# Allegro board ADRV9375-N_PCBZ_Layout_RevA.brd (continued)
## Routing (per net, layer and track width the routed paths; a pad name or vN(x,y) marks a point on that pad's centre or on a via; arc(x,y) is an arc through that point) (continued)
VDD_IF: length 250.6
  TOP w0.203: U403.8 117.21,60.84 v1(117.49,60.57)
  TOP w0.254: U101.M12 v2(38.04,50.78)
  TOP w0.305: U702.1 51.41,16.64 51.01,17.05 ; v1(56.78,24.56) 55.25,26.09 R606.1 ; R739.2 50.3,16.65 ; R808.1 R809.1 137.92,53.04 v2(137.83,52.96) ; R510.1 93.34,49.45 98.32,49.45 100.09,51.22 v1(100.09,52.12) 100.09,52.69 R512.1 ; U702.2 51.35,15.99 51.03,16.31 ; v1(123.51,32.78) 122.53,33.76 U404.1 120.98,33.76 120.51,34.24 120.51,34.57 120.01,35.06 U404.4 ; U405.8 v1(122.74,66.3) ; v1(97.05,57.64) 97.56,57.13 R513.1 ; v1(117.49,60.57) 118.64,60.57 118.84,60.76 U405.1 ; R511.1 v1(94.81,57.64)
  TOP w0.394: v2(132.75,25.02) 132.75,25.02 R503.1 ; P504.1 v1(43.47,72.38)
  TOP w0.508: 47,14.21 P707.1 ; P707.1 45.92,15.29 ; P707.1 48.08,15.29 ; P707.1 47,16.37
  TOP w0.762: v1(131.48,22.48) 131.45,22.45 R738.2
  L3_PWR w0.508: v1(100.09,52.12) 100.09,54.61 v1(97.05,57.64) 97.05,57.93 96.52,58.46 95.64,58.46 v1(94.81,57.64)
  L3_PWR w0.635: 123.51,29.8 v1(123.51,32.78) ; 123.51,29.8 122.21,28.49 119.45,28.49 118.91,27.96 95.23,27.96 93.51,29.67 85.83,29.67 85.37,30.12 80.03,30.12 v1(78.75,31.41) 77.87,31.41 v1(77.86,31.42) v1(77.1,31.42) ; 123.51,29.8 127.04,26.27 131.5,26.27 v2(132.75,25.02) 132.75,23.75 v1(131.48,22.48)
  L12_PWR w0.203: 56.78,22.65 v1(56.78,24.56)
  L12_PWR w0.508: 115.2,53.13 115.2,59.48 116.28,60.57 v1(117.49,60.57) ; 45.92,15.29 P707.1 ; P707.1 48.08,15.29 ; P707.1 47,14.21 ; P707.1 47,16.37 ; v1(122.74,66.3) 122.74,62.49 125.36,59.86 125.36,52.88
  L12_PWR w0.762: 76.08,55.67 48.27,55.67 45.53,52.94 43.63,52.94 41.47,50.78 v2(38.04,50.78) ; v1(43.47,72.38) 45.56,74.47 68.34,74.47 69.99,72.82 69.99,68.5 71.38,67.1 71.38,61.39 72.65,60.12 76.97,60.12 78.5,58.59 78.5,57.7
  BOTTOM w0.305: C642.1 R502.1 ; C642.1 38.05,50.79 v2(38.04,50.78) ; C642.1 38.05,52.33 C643.1
  BOTTOM w0.394: v1(125.61,36.88) 125.61,36.24 123.51,34.14 v1(123.51,32.78) 123.26,32.78 122.7,33.33 C415.2 ; P801.K40 v1(131.48,22.48) ; P801.J39 v2(132.75,25.02) ; v1(122.74,66.3) 122.81,66.23 C417.2
  BOTTOM w0.508: C734.2 49.64,16.06 C735.2
  BOTTOM w0.762: C734.2 48.87,15.29 P707.1
VDD_IF_LDO: length 2.9
  TOP w0.254: U702.5 57.63,14.69 58.1,15.16 58.1,16.32
  TOP w0.305: U702.7 56.66,16.06
  vias: v1(57.41,17.5) v1(58.47,18.72) v1(58.43,17.45) v1(58.94,18.08) v1(59.45,18.72) v1(59.45,17.51)
VDDA_1P8_1: length 8.1
  TOP w0.127: L306.1 36.39,34.2
  TOP w0.394: 36.78,34.2 35.77,34.2 T306.2 T310.2
  TOP w0.508: 36.78,34.2 37.21,34.2 C327.1 37.6,34.21 37.79,34.02 v1(38.57,34.02) v1(38.57,34.73) v1(38.57,35.44)
  BOTTOM w0.508: v1(38.57,34.02) v1(38.57,34.73) v1(38.57,35.44) 38.57,36.81 L341.2
VDDA_1P8_2: length 6.6
  TOP w0.127: L305.1 33.28,59.35
  TOP w0.394: T309.2 T305.2 33.91,59.35 32.9,59.35
  TOP w0.508: 32.9,59.35 32.47,59.35 C322.1 32.05,59.34 31.93,59.22 v1(31.45,59.22) v1(31.45,59.93) v1(31.45,60.64)
  BOTTOM w0.508: v1(31.45,59.22) v1(31.45,59.93) v1(31.45,60.64) 31.46,60.64 L340.2
VDDA_CALPLL: length 17.7
  TOP w0.254: v2(33.24,43.58) U101.G4
  L7_SIG w0.203: v2(33.24,43.58) 33.5,43.58 33.88,43.19 34.16,43.19 34.43,42.93 34.43,41.58
  L7_SIG w0.394: 34.43,41.58 34.43,36.88 33.03,35.48 32.49,35.48 31.89,34.88 v1(31.89,33.19)
  BOTTOM w0.305: v2(33.24,43.58) 33.24,43.69 33.62,44.07 C615.1
  BOTTOM w0.508: v1(31.89,33.19) 31.89,32.9 32.78,32.01 32.78,30.65 E602.2
VDDA_CLK: length 4.7
  TOP w0.254: v2(38.84,41.18) U101.N1
  BOTTOM w0.305: E603.2 41.03,40.76 C616.1 ; v2(38.84,41.18) 38.89,41.12 C617.1 40.47,41.12 40.86,40.74
  BOTTOM w0.394: C616.1 40.86,40.74
VDDA_CLKSYNTH: length 23.2
  TOP w0.254: v2(33.24,45.18) U101.G6
  L3_PWR w0.127: v2(33.24,45.18) 33.66,44.76 34.2,44.76 34.42,44.53 34.42,41.33 36.06,39.68 36.42,39.68 36.97,39.14 39.99,39.14 41.54,40.69 47,40.69 v1(47.25,40.43)
  BOTTOM w0.305: v2(33.24,45.18) 33.23,45.18 C619.1 ; v1(47.25,40.43) 47.17,40.35 E604.2 46.08,40.36 C618.1
VDDA_DES: length 38.8
  TOP w0.254: v2(39.64,48.38) U101.P9 v2(39.64,47.58) ; U101.N9 v2(38.84,48.38)
  BOTTOM w0.305: C653.1 38.76,49.91 38.76,49.6 38.42,49.26 C654.1 38.42,48.8 v2(38.84,48.38) v2(39.64,48.38) 39.64,48.05 v2(39.64,47.58)
  BOTTOM w0.508: 39.64,48.05 39.71,48.13 48.95,48.13 52.71,44.37 55,44.37 59.73,39.64 59.73,38.32 61.55,36.5 61.73,36.5 62.6,35.63 C652.1 62.23,33.93 60.05,33.93 E613.2
VDDA_RXLO: length 17
  TOP w0.254: U101.C6 v2(30.04,45.18)
  L12_PWR w0.508: v3(25.66,43.99) 21.6,39.92 v1(20.96,39.92)
  BOTTOM w0.203: C621.1 28.46,45.18
  BOTTOM w0.305: C620.1 26.45,45.5 27.2,45.5 27.52,45.18 v2(30.04,45.18)
  BOTTOM w0.394: C620.1 26.17,45.51 25.79,45.13 25.79,44.12 v3(25.66,43.99)
  BOTTOM w0.508: v1(20.96,39.92) 20.71,40.18 20.71,40.5 20.29,40.92 17.76,40.92 E605.2
VDDA_RXSYNTH: length 25.6
  TOP w0.254: U101.G9 v2(34.04,47.58)
  L5_SIG w0.114: v2(34.04,47.58) 33.57,47.11 33.57,46.12 34.39,45.3
  L5_SIG w0.127: 34.39,45.3 34.39,41.1
  L5_SIG w0.203: 43.4,40.98 41.83,40.98 39.99,39.14 37.02,39.14 36.44,39.72 35.77,39.72 34.39,41.1
  L5_SIG w0.305: v1(45.6,38.15) 45.6,38.63 45.81,38.83 45.81,39.75 44.57,40.98 43.4,40.98
  BOTTOM w0.305: v1(45.6,38.15) 45.6,37.64 45.87,37.37 C622.1 E606.2 ; C623.1 34.07,47.54 v2(34.04,47.58)
VDDA_RXTX: length 33.8
  TOP w0.203: v2(33.24,42.78) U101.F2
  L10_SIG w0.203: 33.66,42.07 33.24,42.49 v2(33.24,42.78) 33.29,42.72 33.56,42.72 33.88,42.39 34.16,42.39 34.42,42.13 34.42,41.82 34.05,41.45 34.03,41.45 33.66,41.82 33.66,42.07
  L10_SIG w0.394: 34.03,41.45 34.68,40.79 34.68,34.97 35.7,33.96 35.7,30.97 36.93,29.74 36.97,29.74 39.74,26.97 40.9,26.97 v1(41.67,26.21) v1(42.43,26.21)
  BOTTOM w0.305: v2(33.24,42.78) 33.47,42.78 33.75,43.06 C610.1 35.26,43.06 C609.1
  BOTTOM w0.394: v1(41.67,26.21) v1(42.43,26.21) 43.95,26.21 44.71,26.97 C608.1 48.27,26.97
VDDA_RXVCO: length 21.4
  TOP w0.254: U101.C7 v2(30.04,45.98)
  L12_PWR w0.394: v1(24.16,44.5) 24.66,45 24.9,45 26.42,46.53 v3(27.19,46.53)
  BOTTOM w0.305: C624.1 27.96,46.78 28.33,46.78 28.62,46.49 C625.1 29,46.49 29.52,45.98 v2(30.04,45.98)
  BOTTOM w0.394: v1(24.16,44.5) 24.01,44.35 24.01,43.99 23.12,43.1 11.57,43.1 11.44,42.97 ; v3(27.19,46.53) 27.58,46.92 C624.1
VDDA_SER: length 31.6
  TOP w0.254: v2(39.64,46.78) U101.P8 v2(38.84,46.78) U101.N8
  BOTTOM w0.305: v2(38.84,46.78) v2(39.64,46.78) 39.96,46.78 C613.1
  BOTTOM w0.394: C612.1 40.2,45.56 C613.1
  BOTTOM w0.508: E601.2 54.33,33.93 56.52,33.93 C611.1 56.88,38.8 53.9,41.79 51.36,41.79 48.61,44.54 48.61,44.8 47.63,45.77 46.24,45.77 46.16,45.69 40.48,45.69 40.47,45.69 C612.1
VDDA_SNRXSYNTH: length 23.4
  TOP w0.254: U101.G7 v2(34.04,46.78)
  L12_PWR w0.127: 30.48,47.99 31,47.99 31.11,48.1 33.23,48.1 33.61,47.73 33.61,47.21 v2(34.04,46.78)
  L12_PWR w0.394: v1(21.92,49.32) 22.68,50.08 25.59,50.08 27.11,48.56 29.35,48.56 29.91,47.99 30.48,47.99
  BOTTOM w0.305: v2(34.04,46.78) 34.11,46.71 C627.1
  BOTTOM w0.394: v1(21.92,49.32) 22.11,49.51 22.11,50.08 20.11,52.09 C626.1 18.61,52.09 E608.2
VDDA_SNRXVCO: length 19.6
  TOP w0.254: v2(30.04,43.58) U101.C4
  L12_PWR w0.203: 27.17,42.64 28.52,43.99 29.63,43.99 v2(30.04,43.58)
  L12_PWR w0.508: v1(26.93,38.65) 27.31,39.04 27.31,41.19 27.19,41.31 27.19,41.32 27.17,41.34 27.17,42.64
  BOTTOM w0.203: C629.1 30.17,44.18 30.04,44.05 v2(30.04,43.58)
  BOTTOM w0.508: v1(26.93,38.65) 26.43,35.5 26.23,34.97 C628.1 22.56,29.57 E609.2
VDDA_TXLO: length 29.9
  TOP w0.254: v6(33.24,50.78) U101.F12
  L10_SIG w0.394: v6(33.24,50.78) 33.97,50.78 v5(34.03,50.71)
  L12_PWR w0.203: 29.09,53.51 30.64,51.96 31.66,51.96 33.05,50.57 33.89,50.57 v5(34.03,50.71)
  L12_PWR w0.394: 29.09,53.51 29.09,54.15 24.77,58.47 22.87,58.47 17.76,63.58 17,63.58 16.84,63.42 v1(15,63.42)
  BOTTOM w0.305: C635.1 34.07,50.75 v5(34.03,50.71)
  BOTTOM w0.394: v1(15,63.42) C634.1 13.34,62.78 E612.2
VDDA_TXSYNTH: length 30
  TOP w0.254: v6(33.24,47.58) U101.G8
  L10_SIG w0.127: v6(33.24,47.58) 32.85,47.97 29.81,47.97 29.6,48.18 29.6,48.56 29.44,48.72 28.78,48.72 28.74,48.76
  L10_SIG w0.254: 28.74,48.76 27.97,48.76 27.57,49.16 27.57,50.2 27.82,50.46 27.82,52.73 v1(28.08,52.98) 28.08,53.39 25.16,56.31 22.36,56.31 22.11,56.56 20.58,56.56 19.33,55.31 15.3,55.31 v1(15.2,55.21)
  BOTTOM w0.305: C633.1 28.25,53.15 v1(28.08,52.98)
  BOTTOM w0.394: E611.2 13.73,55.16 C632.1 13.94,55.21 v1(15.2,55.21)
VDDA_TXVCO: length 32.5
  TOP w0.254: v6(33.24,49.18) U101.F11
  L5_SIG w0.203: v5(34.04,48.38) 33.66,47.99 30.68,47.99 30.46,48.22 30.46,48.52 30.18,48.79 27.98,48.79 27.06,49.71
  L5_SIG w0.305: v5(34.04,49.21) 34.01,49.18 v6(33.24,49.18)
  L5_SIG w0.394: v1(15,59.8) 16.11,58.69 19.72,58.69 22.3,56.12 22.3,52.87 25.46,49.71 27.06,49.71
  BOTTOM w0.305: v5(34.04,48.38) 34.04,48.38 34.04,48.81 ; 34.04,48.81 v5(34.04,49.21) ; 34.04,48.81 C631.1
  BOTTOM w0.394: C630.1 13.94,59.79 12.57,59.79 ; C630.1 12.58,59.8 12.57,59.79 ; C630.1 v1(15,59.8) ; 12.57,59.79 E610.2
1P3_BUCK_OUT: length 25.4
  L8_SIG w0.394: v1(77.64,19.39) v1(76.87,19.39) v1(76.11,19.39) 75.41,20.1 75.41,31.12 77.23,32.94 84.4,32.94 v1(85.18,33.72)
  BOTTOM w0.394: R705.1 85.59,33.31 v1(85.18,33.72)
3P3V_CLK: length 43.2
  TOP w0.203: v1(119.82,32.83) 119.82,33.58 U404.6
  TOP w0.305: U405.14 v1(118.84,66.3)
  TOP w0.394: C435.2 v1(92.04,79.63) ; C425.2 83.31,69.86 v1(83.2,69.75) ; C422.2 v1(83.24,76.33) ; C414.2 74.91,79.05 v1(74.93,79.04) ; C421.2 v1(83.24,77.83) ; C437.2 v1(89.04,79.63) ; C434.2 v1(93.54,79.63) ; C432.2 v1(95.34,73.83) ; C438.2 v1(87.54,79.63) ; C439.2 v1(86.04,79.63) ; C424.2 v1(83.28,73.33) ; C430.2 v1(95.34,70.83) ; v1(85.94,67.54) 85.94,67.54 86.04,67.63 C426.2 ; C436.2 v1(90.54,79.63) ; C428.2 v1(93.54,67.53) ; C429.2 v1(95.34,69.33) ; v1(83.22,74.83) C423.2 ; C431.2 v1(95.34,72.33) ; C427.2 v1(89.04,67.53) ; C433.2 v1(95.34,75.33)
  BOTTOM w0.203: 94.41,70.83 94.41,70.83 U401.69 ; U401.51 92.04,78.53 ; U401.36 84.34,77.83 ; U401.16 86.04,68.45 ; 89.04,68.45 89.04,68.45 U401.10 ; U401.1 v1(93.54,67.53) ; U401.63 94.24,73.83 ; U401.45 89.04,78.53
  BOTTOM w0.254: 86.04,68.45 86.04,67.63 85.94,67.54 v1(85.94,67.54) ; U401.60 v1(95.34,75.33) ; 89.04,78.53 v1(89.04,79.63) ; 89.04,68.45 v1(89.04,67.53) ; U401.33 v1(83.24,76.33) ; v1(95.34,69.33) U401.72 ; 94.24,73.83 v1(95.34,73.83) ; U401.27 v1(83.28,73.33) ; U401.39 v1(86.04,79.63) ; 94.41,70.83 v1(95.34,70.83) ; 84.34,77.83 v1(83.24,77.83) ; v1(87.54,79.63) 87.54,79.63 U401.42 ; U401.20 83.82,69.83 83.8,69.81 83.72,69.81 83.66,69.75 v1(83.2,69.75) ; U401.48 v1(90.54,79.63) ; U401.66 v1(95.34,72.33) ; 92.04,78.53 v1(92.04,79.63) ; U401.30 v1(83.22,74.83) ; U401.54 v1(93.54,79.63)
  BOTTOM w0.305: U402.5 v1(74.93,79.04)
  BOTTOM w0.394: C416.2 v1(119.82,32.83) ; C420.1 93.55,79.63 v1(93.54,79.63) ; C418.2 118.87,66.26 v1(118.84,66.3) ; R416.1 82.98,69.53 v1(83.2,69.75)
  vias: v1(109.99,31.73) v1(109.99,30.97) v1(110.88,31.73) v1(110.88,30.97) v1(111.77,31.73) v1(111.77,30.97)
3P3V_VCO: length 65
  BOTTOM w0.305: 127.01,74.97 127.01,74.96 C738.2
  BOTTOM w0.394: v1(109.41,76.5) C405.2 Y402.6 Y403.4 Y401.6
  BOTTOM w0.508: R408.2 124.35,72.91 124.82,73.39 125.56,74.13 v1(125.56,74.97) v1(126.23,74.97) 127.53,74.97 130.06,72.44 130.06,54.83 126.97,51.74 126.5,51.74 120.53,45.77 118.75,45.77 116.21,43.23 114.18,43.23 111.13,40.18 109.86,40.18 107.97,38.29 103.91,38.29 E706.2
3P3VAUX: length 101.7
  TOP w0.305: U801.8 C803.2 125.17,31.99 125.17,31.99 C804.1 127.52,31.96 v1(127.68,31.96) ; U601.10 v1(45.49,22.29) ; U601.17 U601.16 ; R818.2 113.21,33.43 v1(112.97,33.67) ; R822.2 v1(113.8,28.75) ; R820.2 v1(113.8,30.53)
  TOP w0.635: v7(51.2,20.37) 51.2,21.64 50.55,22.29 U601.16
  L10_SIG w0.394: v1(45.49,22.29) 46.4,21.38 50.18,21.38 v7(51.2,20.37)
  L10_SIG w0.762: v1(112.97,33.67) 113.8,32.83 v1(113.8,30.53) v1(113.8,28.75) 113.8,21.51 106.05,13.76 61.6,13.76 59.19,16.18 57.03,16.18 52.84,20.37 v7(51.2,20.37)
  BOTTOM w0.394: C649.1 50.22,21.07 50.91,20.37 v7(51.2,20.37) 51.19,20.38 C648.1 ; P801.D32 v2(139.1,33.91)
ADP5054_EN: length 108.4
  TOP w0.305: v1(79.68,31.76) 79.66,31.77 R702.1
  L8_SIG w0.394: v1(79.68,31.76) 79.73,31.81 97.31,31.81 98.31,32.81 115.71,32.81 116.34,32.18 119.54,32.18 119.55,32.17 120.09,32.17 120.1,32.18 121.39,32.18 121.66,32.45 122.42,32.45 122.82,32.05 126.25,32.05 127.56,30.74 135.52,30.74 137.17,32.39 137.17,32.89 141.39,37.12 141.89,37.12 143.52,38.74 143.52,38.78 143.57,38.84 143.57,72.45 142.46,73.57 v2(140.3,73.57)
  BOTTOM w0.394: v2(140.3,73.57) 139.74,73.01 P801.D1
ADP5054_VREG: length 20.4
  TOP w0.394: R703.2 87.86,20.73 87.86,20.99 v1(88.25,21.38) 88.95,22.08 90.64,22.08 91.04,21.68 91.04,21.53 v1(91.07,21.5) 91.4,21.83 91.4,29.02 v1(89.62,30.8)
  BOTTOM w0.203: U701.44 88.75,29.92 89.03,30.2 ; U701.45 89.25,29.98 89.03,30.2 ; 89.03,30.2 v1(89.62,30.8) 89.7,30.87 C702.2
  BOTTOM w0.254: U701.13 90.75,21.82 v1(91.07,21.5) ; U701.18 v1(88.25,21.38)
AUXADC_0: length 66
  TOP w0.254: U101.E13 v6(31.64,51.58)
  L5_SIG w0.114: v6(31.64,51.58) 31.97,51.24 32.79,51.24 34.68,53.13 34.68,56.56 36.65,58.53 37.86,58.53 39.82,60.5 44.26,60.5 44.38,60.38 44.38,60.34 44.68,60.04 45.65,60.04 46.14,60.53 47.22,60.53 47.71,60.04 68.38,60.04 70.3,61.96 70.3,66.02 72.46,68.18 79.13,68.18 81.29,66.02 P501.3
  BOTTOM w0.203: C506.1 P501.3
AUXADC_1: length 88.3
  TOP w0.254: U101.C11 v6(30.04,49.98)
  L5_SIG w0.114: v6(30.04,49.98) 29.6,50.41 29.6,51.69 29.38,51.91 29.04,51.91 28.77,52.18 28.77,52.9 25.66,56.01 25.66,60.24 26.51,61.09 26.53,61.09 26.99,61.56 26.99,66.4 27.44,66.85 28.08,66.85 28.77,67.55 28.77,69.07 30.81,71.1 33.98,71.1 36.33,68.75 45.86,68.75 47,69.9 47.8,69.9 47.84,69.87 54.9,69.87 55.82,70.79 61.86,70.79 63.15,69.5 65.82,69.5 66.29,69.02 67.84,69.02 68.17,69.35 80.43,69.35 82.46,67.33 82.46,63.58 P501.4
  BOTTOM w0.203: C505.1 P501.4
AUXADC_2: length 64.2
  TOP w0.254: U101.C12 v6(30.04,50.78)
  L5_SIG w0.114: P501.5 78.75,66.02 77.29,67.48 72.84,67.48 70.88,65.52 70.88,61.99 70.88,61.99 70.88,61.56 70.88,61.56 70.88,61.04 69.19,59.36 46.93,59.36 46.68,59.61 39.76,59.61 38.01,57.86 36.94,57.86 35.19,56.11 35.19,53.13 33.97,51.91 33.9,51.91 33.7,51.72 32.39,50.4 30.41,50.4 v6(30.04,50.78)
  BOTTOM w0.203: 78.75,66.42 P501.5
AUXADC_3: length 64.8
  TOP w0.254: U101.D11 v6(30.84,49.98)
  L5_SIG w0.114: v6(30.84,49.98) 31.17,49.64 32.58,49.64 32.9,49.96 32.9,50.12 33.1,50.31 33.38,50.31 33.7,50.63 33.7,50.85 33.9,51.05 34.12,51.05 34.43,51.35 34.43,51.86 35.63,53.07 35.63,55.12 36.28,55.77 36.39,55.77 37.44,56.82 39.25,56.82 40.59,58.15 42.62,58.15 43.5,59.04 45.1,59.04 45.42,58.72 69.48,58.72 71.38,60.63 71.38,65.13 73.22,66.98 75.89,66.98 77.42,65.45 77.42,63.74 P501.6
  BOTTOM w0.203: 78.75,60.93 P501.6
BAL_TX1+: length 0.5
  TOP w0.127: L305.2 33.79,58.82
BAL_TX2+: length 0.7
  TOP w0.127: T306.3 35.88,34.73 L306.2
BAL_TX_OUT1: length 1
  TOP w0.203: 33.92,60.94 C305.1 ; T305.1 33.92,60.36
  TOP w0.394: 33.92,60.36 33.92,60.94
BAL_TX_OUT2: length 1
  TOP w0.203: T306.1 35.76,33.19 ; R304.1 35.76,32.62
  TOP w0.394: 35.75,33.01 35.75,33 ; 35.76,32.62 35.76,33.19
CLK+: length 7.5
  BOTTOM w0.203: 92.72,63.47 92.28,63.47 92.06,63.69 92.06,64.42 92.97,65.32 92.97,67.76 93.04,67.83 U401.2 ; 92.72,63.47 R406.1 ; 92.72,63.47 93.54,63.47 C402.2
CLK-: length 8.1
  BOTTOM w0.203: 92.72,63.12 92.13,63.12 91.7,63.55 91.7,64.56 92.61,65.47 92.61,67.76 92.54,67.83 U401.3 ; 92.72,63.12 93.54,63.12 C403.2 ; 92.72,63.12 R406.2
CLK_RESETB: length 109.6
  TOP w0.203: U404.5 119.43,34.41 119.1,34.74 119.1,35.38 119.33,35.62 v1(120.18,35.62)
  L7_SIG w0.114: v1(120.18,35.62) 120.18,35.45 120.91,34.72 125.36,34.72 127.64,37 135.24,37 137.37,39.14 137.37,39.18 137.64,39.45 137.69,39.45 138.87,40.64 138.87,41.25 142.25,44.62 142.25,59.61 141.94,59.92 137.82,59.92 137.68,59.77 134.72,59.77 132.09,62.4 127.39,62.4 125.23,64.56 117.61,64.56 114.94,67.23 94.75,67.23 92.92,69.06 v1(83.45,69.06)
  BOTTOM w0.203: v1(83.45,69.06) 83.72,69.33 U401.19
  BOTTOM w0.394: v1(83.45,69.06) 82.93,68.54 R416.2
CLK_SYSREF_REQUEST: length 32.4
  TOP w0.203: U405.13 v1(119.49,69.23)
  L7_SIG w0.114: v1(119.49,69.23) 117.04,71.67 102.75,71.67 99.96,74.47 98.31,74.47 96.53,76.24 v1(96.53,77.8)
  BOTTOM w0.254: v1(96.53,77.8) 95.57,76.83 94.92,76.83 U401.57 ; R417.2 97.17,77.8
  BOTTOM w0.394: 97.17,77.8 v1(96.53,77.8)
COMP_OUT: length 4.9
  BOTTOM w0.203: Y401.5 Y402.5 111.38,73.96 110.59,73.18 R411.1
DEV_CLK_IN+: length 66.7
  BOTTOM w0.203: R501.2 32.21,48.56 ; 32.21,48.56 32.21,49.34 arc(32.44,50.7) 33.1,51.9 arc(35.41,53.73) 38.29,54.35 42.12,54.35 arc(44.94,55.52) 46.11,58.34 46.11,63.14 arc(47.52,66.56) 50.94,67.97 50.94,67.97 arc(58.87,68.59) 66.64,70.3 arc(73.86,71.88) 81.24,72.41 81.75,72.41 ; 32.21,48.56 32.21,48.29 arc(32.24,48.12) C502.1 ; 81.75,72.41 R425.1 ; 81.75,72.41 83.63,72.41 83.72,72.33 U401.25
DEV_CLK_IN-: length 67.3
  BOTTOM w0.203: 31.85,48.56 31.85,49.34 arc(32.1,50.82) 32.83,52.13 arc(35.26,54.05) 38.29,54.7 42.12,54.7 arc(44.69,55.77) 45.75,58.34 45.75,63.14 arc(47.27,66.81) 50.94,68.32 arc(58.82,68.94) 66.54,70.64 arc(73.81,72.23) 81.24,72.77 81.75,72.77 ; 31.85,48.56 R501.1 ; 31.85,48.56 31.85,48.29 arc(31.81,48.12) C501.1 ; U401.26 83.68,72.83 83.62,72.77 81.75,72.77 ; 81.75,72.77 R425.2
DIR_CLK+: length 4.6
  BOTTOM w0.203: T401.1 98.43,64.56 97.99,64.12 97.49,64.12 R403.2 96.85,63.47 96.02,63.47 ; 96.02,63.47 95.2,63.47 C402.1 ; 96.02,63.47 R405.1
DIR_CLK-: length 4.6
  BOTTOM w0.203: T401.3 98.48,62.02 98.01,62.49 97.46,62.49 R404.1 96.83,63.12 96.02,63.12 ; R405.2 96.02,63.12 ; 96.02,63.12 95.2,63.12 C407.1
EPROM_A0: length 115.9
  TOP w0.203: U601.11 47.52,20.89 v1(46.87,20.24)
  TOP w0.305: v1(119.89,30.91) 118.85,31.95 U801.1 116.61,31.95 115.77,32.79 R819.2 R818.1
  L8_SIG w0.114: v1(119.89,30.91) 119.39,30.91 114.31,25.83 102.5,25.83 94.18,17.51 81.86,17.51 80.78,16.43 57.67,16.43 52.34,21.76 48.39,21.76 v1(46.87,20.24)
  L10_SIG w0.114: v2(141.64,30.1) 139.72,30.1 137.37,27.75 137.37,27.55 136.53,26.72 124.08,26.72 v1(119.89,30.91)
  BOTTOM w0.394: P801.C34 v2(141.64,30.1)
EPROM_A1: length 115.9
  TOP w0.203: v1(48.14,20.24) 48.52,20.62 U601.13
  TOP w0.305: v1(118.85,31.09) 118.64,31.3 U801.2 116.46,31.3 116.11,31.65 R821.2 R820.1
  L8_SIG w0.114: v1(118.85,31.09) 118.85,31.13 119.26,31.54 120.02,31.54 120.53,31.03 120.53,30.53 114.31,24.3 105.8,24.3 97.23,15.73 57.61,15.73 52.21,21.13 49.03,21.13 v1(48.14,20.24)
  L10_SIG w0.114: v1(118.85,31.09) 123.98,25.95 137.5,25.95 v2(140.37,28.83)
  BOTTOM w0.394: P801.D35 v2(140.37,28.83)
FMC_CLK_RESETB: length 24
  TOP w0.305: v2(140.37,41.53) 138.57,39.73 138.57,37.52 136.91,35.86 130.82,35.86 130.37,35.41 123.77,35.41 122.77,34.41 U404.2
  BOTTOM w0.394: v2(140.37,41.53) P801.D26
FMC_SYSREF_REQUEST: length 48.8
  TOP w0.203: U405.2 v1(119.49,63.29)
  L8_SIG w0.114: v2(140.37,38.99) 139.35,40.01 139.35,46.94 140.22,47.8 140.97,47.8 141.48,48.31 141.74,48.31 142.25,48.82 142.25,57.07 140.65,58.67 132.77,58.67 129.4,62.05 126.86,62.05 125.84,61.03 121.74,61.03 v1(119.49,63.29)
  BOTTOM w0.394: v2(140.37,38.99) P801.D27
FMCA_SCL: length 107.4
  TOP w0.203: U601.15 49.52,20.76 v1(50.05,20.24)
  TOP w0.305: v1(121.8,31.03) 122.19,30.65 U801.6
  L8_SIG w0.114: v1(121.8,31.03) 120.91,30.15 120.91,29.89 114.25,23.22 114.25,21.07 108.21,15.03 57.41,15.03 53.73,18.72 51.57,18.72 v1(50.05,20.24)
  L10_SIG w0.114: v1(121.8,31.03) 122.31,31.03 122.68,31.41 130.69,31.41 133.87,34.59 141.06,34.59 v2(141.64,35.18)
  BOTTOM w0.394: v2(141.64,35.18) P801.C30
FMCA_SDA: length 110
  TOP w0.203: U601.14 v1(49.02,20.24)
  TOP w0.305: v1(121.82,30) U801.5
  L8_SIG w0.114: v1(49.02,20.24) 49.02,18.85 53.6,14.27 108.59,14.27 114.75,20.43 114.75,22.84 121.82,29.91 v1(121.82,30)
  L10_SIG w0.114: v2(141.64,33.91) 141.64,33.86 137.3,29.51 127.52,29.51 126.88,28.88 125.1,28.88 123.98,30 v1(121.82,30)
  BOTTOM w0.394: v2(141.64,33.91) P801.C31
FMCA_VADJ: length 13.2
  TOP w0.762: R738.1 131.44,19.44 ; 131.44,19.44 131.45,19.43 C732.1 ; 131.44,19.44 129.45,19.44 TP812.1
  L12_PWR w0.508: 128.3,19.57 TP812.1 ; TP812.1 129.31,20.59 ; TP812.1 128.3,21.61 ; TP812.1 127.28,20.59
  BOTTOM w0.394: P801.G39 v2(136.56,23.75) ; P801.H40 v2(134.02,23.75) ; P801.E39 v2(139.1,23.75) ; P801.F40 v2(137.83,22.48)
FMCA_VCC_3P3V: length 7.7
  L12_PWR w0.508: TP816.1 129.39,23.89 ; TP816.1 127.36,23.89 ; TP816.1 128.37,22.87 ; TP816.1 128.37,24.91
  BOTTOM w0.394: P801.D40 v2(140.37,22.48) ; P801.D36 v2(140.37,27.56) ; P801.D38 v2(140.37,25.02) ; P801.C39 v2(141.64,23.75)
FMCA_VCC_12P0V: length 5.9
  TOP w0.508: TP815.1 121.29,27.61 ; TP815.1 121.29,25.57 ; TP815.1 122.31,26.59 ; TP815.1 120.28,26.59
  BOTTOM w0.394: P801.C37 v2(141.64,26.29) ; P801.C35 v2(141.64,28.83)
FPGA_AUX_CLK+: length 49.2
  TOP w0.203: v1(102.28,75) 102.3,74.98 121.93,74.98 122.88,74.02 126.5,74.02 126.7,74.23 130.43,74.23 131.58,73.07 134.18,73.07 134.97,72.28 137.82,72.28 138.97,71.14 139.16,71.14 140.22,70.09 C805.1
  BOTTOM w0.203: v1(102.28,75) 102.05,74.76 99.07,74.76 ; 99.07,74.76 95.1,74.76 95.04,74.83 U401.61 ; 99.07,74.76 R429.1
FPGA_AUX_CLK-: length 49.2
  TOP w0.203: v1(102.28,74.18) 102.72,74.62 121.78,74.62 122.73,73.67 126.65,73.67 126.85,73.87 130.28,73.87 131.43,72.72 134.04,72.72 134.82,71.93 137.68,71.93 138.82,70.79 139.02,70.79 139.86,69.94 139.86,69.76 139.71,69.6 139.71,69.45 139.58,69.33 C806.1
  BOTTOM w0.203: 99.07,74.4 99.07,74.41 99.68,74.41 102.06,74.41 v1(102.28,74.18) ; 99.07,74.4 95.11,74.4 95.04,74.33 U401.62 ; 99.07,74.4 R429.2
FPGA_REF_CLK+: length 82
  TOP w0.203: v1(97.65,73.49) 98.35,73.49 103.51,78.66 132.22,78.66 133.8,77.07 141.23,77.07 145.93,72.37 145.93,62.59 146.14,62.39 146.14,61.27 145.25,60.39 145.25,51.27 144.55,50.56 143.47,50.56 143.27,50.36 C801.2
  BOTTOM w0.203: v1(97.65,73.49) 97.41,73.26 96.63,73.26 ; R422.1 96.63,73.26 ; 96.63,73.26 95.11,73.26 95.04,73.33 U401.64
FPGA_REF_CLK-: length 82
  TOP w0.203: C802.2 142.57,49.01 142.76,49.2 142.76,49.28 142.91,49.44 142.91,50.51 143.32,50.92 144.4,50.92 144.89,51.41 144.89,60.54 145.78,61.42 145.78,62.24 145.58,62.45 145.58,72.23 141.09,76.72 133.66,76.72 132.07,78.3 103.66,78.3 98.49,73.14 98.11,73.14 v1(97.65,72.68)
  BOTTOM w0.203: U401.65 95.04,72.83 95.11,72.9 96.63,72.9 ; R422.2 96.63,72.9 ; 96.63,72.9 97.43,72.9 v1(97.65,72.68)
FPGA_SYSREF+: length 98.5
  L7_SIG w0.091: v2(136.56,27.56) 136.45,27.56 136.06,27.96 136.06,28.59 139.39,31.92 142,31.92 143.65,33.57 143.65,40.18 144.46,41 144.8,41 146.06,42.25 146.06,44.62 145.3,45.39 145.3,61.01 143.77,62.53 142.23,62.53 137.07,67.69 133.66,67.69 131.07,70.28 122.8,70.28 117.46,75.61 108.53,75.61 107.65,76.49 v1(98.79,76.49)
  BOTTOM w0.203: v1(98.79,76.49) 98.56,76.26 97.33,76.26 96.72,76.26 ; 96.72,76.26 R423.2 ; 96.72,76.26 95.16,76.26 95.09,76.33 94.47,76.33 U401.58
  BOTTOM w0.394: P801.G36 v2(136.56,27.56)
FPGA_SYSREF-: length 98.5
  L7_SIG w0.091: v2(135.29,27.56) 135.6,27.56 135.8,27.76 135.8,28.7 139.28,32.18 141.89,32.18 143.39,33.68 143.39,40.28 144.36,41.25 144.7,41.25 145.81,42.36 145.81,44.52 145.04,45.28 145.04,60.9 143.67,62.28 142.12,62.28 136.96,67.44 133.55,67.44 130.97,70.02 122.69,70.02 117.36,75.36 108.43,75.36 107.54,76.24 99.35,76.24 v1(98.79,75.68)
  BOTTOM w0.203: U401.59 95.09,75.83 95.16,75.9 96.72,75.9 ; 96.72,75.9 97.33,75.9 98.56,75.91 98.57,75.91 v1(98.79,75.68) ; 96.72,75.9 R423.1
  BOTTOM w0.394: P801.G37 v2(135.29,27.56)
GP_INTERRUPT: length 113.4
  TOP w0.254: U101.J5 v6(35.64,45.18)
  TOP w0.394: TP803.1 129.71,59.98 134.18,59.98 134.25,59.91 R803.1
  L7_SIG w0.114: TP803.1 127.72,58.1 122.37,52.75 103.64,52.75 99.83,56.56 89.69,56.56 87.64,54.51 87.64,53.91 86.48,52.75 85.73,52.75 84.89,51.9 84.89,49.87 83.18,48.16 82.8,48.16 78.22,43.58 78.19,43.58 77.88,43.28 77.88,43.25 77.19,42.55 55.15,42.55 54.93,42.78 52.53,42.78 51.98,43.33 46.77,43.33 45.26,44.84 40.14,44.84 40.14,44.84 38.7,44.84 38.37,45.16 38.37,45.32 38.18,45.51 37.9,45.51 37.7,45.32 37.7,45.16 37.38,44.84 35.97,44.84 v6(35.64,45.18)
GPIO_0: length 110.5
  TOP w0.254: U101.K8 v6(36.44,47.58)
  TOP w0.305: R513.2 R517.1 96.26,54.23 P502.2
  L7_SIG w0.114: P502.2 100.15,50.34 126.81,50.34 126.95,50.2 129.07,50.2 129.34,50.46 129.76,50.46 130.01,50.21 133.82,50.21 v2(134.02,50.42)
  L8_SIG w0.114: v6(36.44,47.58) 36.69,47.58 37.08,47.19 39.77,47.19 40.31,46.66 43.15,46.66 43.41,46.92 44.65,46.92 44.74,46.83 45.16,46.83 45.63,47.29 46.91,47.29 47.78,48.16 50.03,48.16 51.19,49.32 66.3,49.32 72.4,55.42 79.61,55.42 79.62,55.41 80.04,55.41 80.05,55.42 81.03,55.42 82.05,56.43 94.88,56.43 96.4,54.91 P502.2
  BOTTOM w0.394: v2(134.02,50.42) P801.H19
GPIO_1: length 125.5
  TOP w0.254: U101.J8 v6(35.64,47.58)
  TOP w0.305: R516.1 98.62,52.37 98.62,52.88 ; R512.2 98.62,52.88 ; 98.62,52.88 95.2,52.88 P502.3
  L7_SIG w0.114: P502.3 96.09,49.31 117.63,49.31 117.64,49.32 130.91,49.32 131.55,48.69 132.56,48.69 132.56,48.69 132.95,48.69 132.95,48.69 133.56,48.69 v2(134.02,49.15)
  L8_SIG w0.114: P502.3 93.86,50.34 91.77,48.24 91.77,44.69 90.56,43.48 90.56,42.97 85.86,38.27 59.32,38.27 58.56,37.51 54.49,37.51 54.11,37.13 45.22,37.13 43.45,38.9 42.05,38.9 40.14,40.81 37.6,40.81 36.78,41.64 36.3,41.64 36.1,41.84 36.1,42.06 34.43,43.74 34.43,46.84 34.75,47.16 35.23,47.16 v6(35.64,47.58)
  BOTTOM w0.394: v2(134.02,49.15) P801.H20
GPIO_2: length 123.6
  TOP w0.254: U101.J7 v6(34.84,45.98)
  TOP w0.305: R511.2 R515.1 93.52,54.43 P502.4
  L7_SIG w0.114: P502.4 94.97,55.2 98.28,55.2 102.54,50.94 123.76,50.94 124.05,51.23 129.81,51.23 130.21,51.64 130.66,51.64 131.2,51.1 135.88,51.1 v2(136.56,50.42)
  L8_SIG w0.114: P502.4 92.47,52.69 92.47,50.47 90.99,49 90.99,46.46 88.04,43.5 88.04,43 84.89,39.84 54.54,39.84 53.6,38.9 47.77,38.9 46.49,40.18 41.41,40.18 39.95,41.64 37.41,41.64 36.71,42.34 36.33,42.34 34.68,43.99 34.68,45.82 v6(34.84,45.98)
  BOTTOM w0.394: v2(136.56,50.42) P801.G18
GPIO_3: length 119.7
  TOP w0.254: U101.K7 v6(36.44,46.78)
  TOP w0.305: R514.1 91.51,49.32 R510.2
  TOP w0.394: P502.5 91.46,51.41 R514.1
  L7_SIG w0.114: P502.5 93.67,49.2 93.69,49.2 94,48.9 94,48.87 95.33,47.53 115.72,47.53 116.16,47.09 118.68,47.09 119.01,47.42 133.83,47.42 133.83,47.42 134.22,47.42 134.22,47.42 134.83,47.42 v2(136.56,49.15)
  L8_SIG w0.114: v6(36.44,46.78) 36.44,45.75 35.97,45.28 35.97,45.04 35.78,44.84 35.63,44.84 35.3,44.52 35.3,44.24 35.63,43.91 35.78,43.91 36.08,43.61 36.08,43.46 36.43,43.11 36.58,43.11 36.9,42.79 36.9,42.64 37.2,42.34 40.01,42.34 41.28,41.07 48.26,41.07 48.77,40.57 52.21,40.57 52.33,40.69 62.33,40.69 62.33,40.68 83.07,40.68 83.37,40.99 83.37,41.25 89.23,47.1 89.23,49.13 91.32,51.23 P502.5
  BOTTOM w0.394: v2(136.56,49.15) P801.G19
GPIO_3P3_0: length 59.1
  TOP w0.254: U101.C1 29.49,40.63 v6(29.35,40.63)
  L8_SIG w0.114: v6(29.35,40.63) 29.24,40.63 28.85,41.02 28.85,41.53 28.46,41.93 28.46,43.74 28.79,44.07 28.79,47.6 29.23,48.04 29.38,48.04 29.39,48.05 29.4,48.05 29.7,48.36 29.7,48.52 29.9,48.71 30.09,48.71 31.3,49.92 31.3,50.12 31.5,50.31 31.66,50.31 33.54,52.19 33.54,54.46 38.81,59.74 39.13,59.74 40.65,61.26 40.65,62.66 46.49,68.5 48.52,68.5 48.78,68.25 49.67,68.25 50.05,68.63 61.48,68.63 64.02,66.09 P503.5
  BOTTOM w0.203: P503.5 64.02,66.37
GPIO_3P3_1: length 52.3
  TOP w0.254: U101.C2 v6(30.04,41.98)
  L8_SIG w0.114: v6(30.04,41.98) 29.65,42.36 29.65,47.72 29.97,48.04 30.18,48.04 30.5,48.36 30.5,48.52 30.7,48.71 30.89,48.71 31.3,49.12 31.3,49.32 31.5,49.51 31.69,49.51 32.04,49.86 32.04,50.11 34.05,52.12 34.05,53.64 36.3,55.89 36.55,55.89 37.47,56.82 39.51,56.82 40.65,57.96 40.65,59.23 43.06,61.64 43.06,63.67 44.97,65.58 45.86,65.58 47.51,67.23 50.3,67.23 50.81,67.74 56.14,67.74 57.41,66.47 59.95,66.47 P503.7
  BOTTOM w0.203: P503.7 61.48,66.37
GPIO_3P3_2: length 43
  TOP w0.254: U101.F1 v6(32.44,41.18)
  L8_SIG w0.114: v6(32.44,41.18) 32.1,41.51 32.1,43.72 32.3,43.91 32.45,43.91 32.85,44.31 32.85,46.86 32.9,46.91 32.9,46.92 33.23,47.24 33.38,47.24 33.57,47.44 33.57,47.66 33.95,48.04 34.18,48.04 34.37,48.24 34.37,48.39 34.78,48.79 35.04,48.79 35.3,49.05 35.3,49.32 35.5,49.51 35.76,49.51 36.1,49.85 36.1,50.12 36.3,50.31 36.56,50.31 36.84,50.6 36.84,52.12 37.44,52.72 40.12,52.72 40.47,52.37 43.44,52.37 45.35,54.28 49.84,54.28 57.67,62.1 57.67,63.67 P503.9
GPIO_3P3_3: length 44.8
  TOP w0.254: U101.D1 31.2,41.54 v6(31.2,41.01)
  L8_SIG w0.114: v6(31.2,41.01) 30.43,41.79 30.43,47.64 30.83,48.04 30.98,48.04 31.3,48.36 31.3,48.52 31.5,48.71 31.66,48.71 32.9,49.96 32.9,50.12 33.1,50.31 33.25,50.31 33.7,50.76 33.7,50.85 33.9,51.05 33.99,51.05 34.5,51.56 34.5,52.83 36.41,54.74 36.7,54.74 36.98,55.01 40.24,55.01 45.98,60.75 45.98,61.9 50.3,66.21 55.13,66.21 P503.11
  BOTTOM w0.203: P503.11 C525.1
GPIO_3P3_4: length 40.6
  TOP w0.254: U101.E1 v6(31.64,41.18)
  L8_SIG w0.114: v6(31.64,41.18) 31.25,41.56 31.25,43.66 31.5,43.91 31.72,43.91 32.05,44.24 32.05,46.95 33.14,48.04 33.38,48.04 33.57,48.24 33.57,48.6 33.82,48.84 34.15,48.84 34.37,49.07 34.37,49.27 34.71,49.6 34.96,49.6 35.3,49.94 35.3,50.12 35.5,50.31 35.67,50.31 35.97,50.62 35.97,52.65 37.35,54.02 42.94,54.02 44.46,55.55 46.75,55.55 52.59,61.39 52.59,63.67 P503.13
  BOTTOM w0.203: P503.13 C526.1
GPIO_3P3_5: length 35
  TOP w0.254: U101.D5 v6(30.84,44.38)
  L8_SIG w0.114: P503.15 48.65,62.28 48.65,60.93 44.82,57.1 44.06,57.1 43.75,56.8 43.75,56.33 41.95,54.53 36.98,54.53 35.3,52.85 35.3,50.76 34.98,50.44 34.65,50.44 33.57,49.36 33.57,49.04 33.38,48.84 33.05,48.84 32.77,48.56 32.77,48.24 32.58,48.04 32.25,48.04 31.23,47.02 31.23,44.77 v6(30.84,44.38)
  BOTTOM w0.203: P503.15 C527.1
GPIO_3P3_6: length 56.1
  TOP w0.254: U101.E14 v6(31.64,52.38)
  L5_SIG w0.114: v6(31.64,52.38) 31.96,52.38 32.3,52.71 32.43,52.71 32.58,52.86 32.58,54.62 31.7,55.5 31.7,56.24 32.23,56.78 32.3,56.78 32.97,57.46 32.97,59.17 34.43,60.63 34.43,61.22 39.17,65.96 45.67,65.96 45.68,65.96 46.1,65.96 46.11,65.96 46.49,65.96 46.68,66.15 48.09,66.15 48.16,66.08 49.36,66.08 49.36,66.09 56.84,66.09 57.54,65.39 57.54,61.9 58.18,61.26 61.99,61.26 62.41,61.68 62.41,61.73 62.75,62.07 62.75,62.91 63.38,63.55 67.95,63.55 P503.2
  BOTTOM w0.203: P503.2 C528.1
GPIO_3P3_7: length 56.9
  TOP w0.254: U101.D12 v6(30.84,50.78)
  L8_SIG w0.114: P503.4 67.83,63.67 67.83,65.32 66.68,66.47 66.43,66.47 61.99,70.91 55.13,70.91 53.98,69.77 44.71,69.77 39.89,64.94 39.89,63.46 34.71,58.28 34.71,57.42 33.7,56.41 33.7,56.4 33.4,56.1 33.39,56.1 33.06,55.77 33.05,55.77 32.75,55.47 32.75,55.04 32.85,54.94 32.85,52.31 32.58,52.04 32.42,52.04 31.97,51.59 31.97,51.44 31.77,51.23 31.29,51.23 v6(30.84,50.78)
  BOTTOM w0.203: P503.4 66.56,60.65
GPIO_3P3_8: length 43.6
  TOP w0.254: U101.D13 v6(30.84,51.58)
  L5_SIG w0.114: v6(30.84,51.58) 31.21,51.95 33.02,51.95 34.3,53.23 34.3,57.9 36.7,60.3 37.21,60.3 38.05,61.13 48.52,61.13 49.03,60.63 63,60.63 64.02,61.64 P503.6
  BOTTOM w0.203: P503.6 64.02,60.65
GPIO_3P3_9: length 62
  TOP w0.254: U101.C13 v6(30.04,51.58)
  L5_SIG w0.114: v6(30.04,51.58) 30.04,52.12 28.97,53.19 28.97,57.55 27.81,58.71 27.81,60.6 27.49,60.93 27.49,66.1 27.82,66.43 28.42,66.43 29.25,67.26 29.25,68.85 30.87,70.47 33.85,70.47 36.27,68.06 39.52,68.06 40.13,67.44 47.97,67.44 48.78,68.25 59.83,68.25 62.62,65.45 62.62,64.18 61.48,63.04 P503.8
  BOTTOM w0.203: P503.8 61.48,60.65
GPIO_3P3_10: length 54.5
  TOP w0.254: U101.D14 v6(30.84,52.38)
  L5_SIG w0.114: v6(30.84,52.38) 30.42,52.38 29.34,53.46 29.34,58.76 29.68,59.1 29.68,59.81 28.2,61.29 28.2,65.29 30.46,67.55 38.93,67.55 39.7,66.79 45.48,66.79 45.68,66.98 48.8,66.98 48.93,67.11 50.29,67.11 50.89,66.51 59.15,66.51 60.21,65.45 60.21,63.67 P503.10
  BOTTOM w0.203: P503.10 C532.1
GPIO_3P3_11: length 32.7
  TOP w0.254: U101.F14 v6(32.44,52.38)
  L5_SIG w0.114: P503.12 55.13,63.67 47.57,63.67 47.28,63.38 40.23,63.38 38.74,61.9 37.79,61.9 36.9,61.01 36.2,61.01 33.8,58.61 33.8,53.68 32.85,52.73 32.85,52.63 32.59,52.38 v6(32.44,52.38)
GPIO_4: length 119.4
  TOP w0.254: U101.K6 v6(36.44,45.18)
  TOP w0.305: R524.1 91.29,54.11 P502.6
  L7_SIG w0.114: P502.6 90.18,52.94 90.18,50.47 94.88,45.77 113.42,45.77 113.72,46.07 117.69,46.07 118.31,45.45 130.47,45.45 133.12,42.8 v2(134.02,42.8)
  L8_SIG w0.114: P502.6 90.12,52.88 90.12,50.66 88.45,49 88.45,48.46 88.15,48.16 87.62,48.16 83.72,44.26 62.93,44.26 61.22,42.55 55.55,42.55 55.44,42.66 54.18,42.66 53.48,41.96 49.67,41.96 49.36,41.65 41.47,41.65 39.87,43.24 38.98,43.24 37.1,43.24 36.9,43.44 36.9,43.59 36.58,43.91 36.41,43.91 36.1,44.22 36.1,44.52 36.44,44.86 v6(36.44,45.18)
  BOTTOM w0.394: v2(134.02,42.8) P801.H25
GPIO_5: length 112.3
  TOP w0.254: U101.K5 v6(36.44,44.38)
  TOP w0.305: R522.1 89.04,51.29 P502.7
  L7_SIG w0.114: P502.7 88.78,48.94 90.56,47.16 90.56,46.53 93.48,43.61 107.23,43.61 107.24,43.61 107.66,43.61 107.67,43.61 117.69,43.61 117.83,43.46 118.26,43.46 118.93,44.14 122.41,44.14 122.69,43.86 131.19,43.86 133.53,41.53 v2(134.02,41.53)
  L8_SIG w0.097: 39.51,43.99 39.89,43.99
  L8_SIG w0.114: 39.89,43.99 40.78,43.1 49.67,43.1 49.92,43.35 53.6,43.35 54.3,44.05 59.88,44.05 61.42,45.58 82.25,45.58 84.46,47.8 85.35,47.8 88.78,51.23 P502.7 ; v6(36.44,44.38) 36.76,44.38 37.15,43.99 39.51,43.99
  BOTTOM w0.394: v2(134.02,41.53) P801.H26
GPIO_6: length 120.8
  TOP w0.254: U101.L5 v6(37.24,44.38)
  TOP w0.305: R523.1 88.82,54.12 P502.8
  L7_SIG w0.114: P502.8 90.62,55.93 98.94,55.93 102.88,51.99 128.92,51.99 129.29,52.36 136.55,52.36 137.03,51.88 137.03,51.84 141.11,47.76 141.11,45.87 v2(141.64,45.34)
  L8_SIG w0.114: P502.8 87.64,52.94 87.64,50.97 86.21,49.55 86.21,49.31 86.1,49.2 82.81,49.2 82.81,49.19 82.65,49.19 80.16,46.71 80.16,46.59 79.66,46.09 60.4,46.09 59.77,45.45 57.85,45.45 56.96,44.56 55.32,44.56 55.19,44.68 49.85,44.68 49.28,44.12 40.52,44.12 39.89,44.75 37.61,44.75 v6(37.24,44.38)
  BOTTOM w0.394: v2(141.64,45.34) P801.C22
GPIO_7: length 119.8
  TOP w0.254: U101.L6 v6(37.24,45.18)
  TOP w0.305: P502.9 86.65,51.14 R519.1
  L7_SIG w0.114: v2(140.37,45.34) 140.37,44.46 137.99,42.08 135.65,42.08 134.49,40.93 132.07,40.93 131.31,41.69 130.7,41.69 130.64,41.63 127.85,41.63 127.14,42.34 121.95,42.34 121.57,41.96 120.06,41.96 119.61,42.41 113.74,42.41 113.42,42.08 93.1,42.08 91.07,44.12 90.43,44.12 89.54,45 89.54,45.64 86.24,48.94 P502.9
  L8_SIG w0.114: v6(37.24,45.18) 37.7,45.64 38.7,45.64 39.76,45.64 40.65,44.75 47.18,44.75 47.21,44.72 48.24,44.72 49.6,46.08 59.38,46.08 60.72,47.42 77.61,47.42 79.76,49.57 79.85,49.57 80.15,49.87 80.15,49.96 80.53,50.34 85.04,50.34 P502.9
  BOTTOM w0.394: P801.C23 v2(140.37,45.34)
GPIO_8: length 146.8
  TOP w0.254: U101.L12 v6(37.24,50.78)
  TOP w0.305: R520.1 86.23,56.32 86.23,54.1 P502.10
  L5_SIG w0.091: P502.10 86.24,55.32 85.93,55.64 85.93,55.89 85.97,55.93 97.29,55.93 99.2,54.02 102.88,54.02 103.13,53.77 123.86,53.77 124.11,53.51 129.95,53.51 131.22,52.24 136.81,52.24 138.81,50.25 138.81,42.57 138.5,42.26 135.96,42.26 135.77,42.45 135.77,43.14 135.64,43.27 135.03,43.27 134.77,43.01 134.77,42.14 134.65,42.01 132.24,42.01 132.12,42.14 132.12,44.42 132.24,44.55 133.37,44.55 133.5,44.42 133.5,43.61 133.63,43.48 134.37,43.48 134.5,43.61 134.5,44.42 134.62,44.55 135.82,44.55 135.94,44.42 135.94,43.74 136.07,43.62 137.23,43.62 137.35,43.49 137.35,42.93 137.23,42.8 v2(136.56,42.8)
  L10_SIG w0.091: v6(37.24,50.78) 37.63,51.17 37.63,51.75 37.05,52.34 37.05,53.49 37.96,54.4 44.46,54.4 46.16,52.7 70.11,52.7 73.44,49.37 79.28,49.37 79.32,49.33 79.95,49.33 79.99,49.37 83.34,49.37 85.04,51.06 85.04,52.88 P502.10
  BOTTOM w0.203: v2(136.56,42.8) P801.G25
GPIO_9: length 117.5
  TOP w0.254: U101.K12 v6(36.44,50.78)
  L5_SIG w0.091: P502.11 83.7,52.37 84.05,52.73 84.27,52.73 84.82,52.18 84.82,50.86 85.72,49.96 115.05,49.96 115.62,50.53 124.52,50.53 127.92,47.13 134.18,47.13 134.5,46.8 134.5,46 134.4,45.9 134.24,45.9 134.02,46.12 v2(134.02,46.61)
  L10_SIG w0.091: P502.11 83.83,51.55 83.95,51.67 83.95,52.56 83.83,52.69 72.87,52.69 68.37,57.2 41.43,57.2 40.57,58.06 37.05,58.06 35.66,56.68 35.66,52.1 35.76,52.01 35.85,52.01 36.08,51.78 36.08,51.13 v6(36.44,50.78)
  BOTTOM w0.203: v2(134.02,46.61) P801.H22
GPIO_10: length 117.5
  TOP w0.254: U101.J12 v6(35.64,50.78)
  L5_SIG w0.091: v2(134.02,45.34) 134.33,45.65 134.51,45.65 134.76,45.89 134.76,46.91 134.28,47.38 128.03,47.38 124.63,50.79 115.52,50.79 114.94,50.21 85.83,50.21 85.07,50.97 85.07,52.29 84.38,52.98 84.12,52.98 83.7,53.4 P502.12
  L10_SIG w0.091: P502.12 83.7,53.03 83.61,52.94 72.98,52.94 68.47,57.45 41.54,57.45 40.67,58.31 36.94,58.31 35.41,56.78 35.41,51.87 35.31,51.77 35.31,51.1 v6(35.64,50.78)
  BOTTOM w0.203: v2(134.02,45.34) P801.H23
GPIO_11: length 117.9
  TOP w0.254: U101.H12 v6(34.84,50.78)
  L5_SIG w0.091: v2(135.29,46.61) 135.62,46.94 135.62,48.35 134.3,49.67 130.6,49.67 128.19,52.08 103.29,52.08 102.69,52.68 85.6,52.68 84.88,53.4 84.88,54.74 84.39,55.22 83.21,55.22 82.59,54.61 82.59,53.45 81.84,52.69 81.39,52.69 81.16,52.46 P502.13
  L7_SIG w0.091: v6(34.84,50.78) 34.85,50.78 34.86,50.79 35.12,50.79 35.52,50.39 39.71,50.39 39.92,50.59 39.92,50.76 40.06,50.9 44.38,50.9 45.86,52.37 70.11,52.37 73.48,55.74 78.66,55.74 79.75,54.64 79.75,53.07 80.14,52.69 81.88,52.69 82.01,52.56 82.01,51.67 81.88,51.55 P502.13
  BOTTOM w0.203: P801.G21 v2(135.29,46.61)
GPIO_12: length 117.8
  TOP w0.254: U101.H11 v6(34.84,49.98)
  L5_SIG w0.091: P502.14 81.16,53.16 81.38,52.94 81.73,52.94 82.34,53.55 82.34,54.72 83.1,55.48 84.5,55.48 85.13,54.84 85.13,53.51 85.71,52.94 102.8,52.94 103.4,52.34 128.29,52.34 130.7,49.92 134.41,49.92 135.88,48.46 135.88,47.29 v2(136.56,46.61)
  L7_SIG w0.091: v6(34.84,49.98) 34.84,50.31 34.51,50.63 34.51,50.91 34.75,51.15 44.28,51.15 45.75,52.62 70.01,52.62 73.37,55.99 78.77,55.99 80.01,54.75 80.01,53.18 80.24,52.94 81.07,52.94 81.16,53.03 P502.14
  BOTTOM w0.203: P801.G22 v2(136.56,46.61)
GPIO_13: length 121.9
  TOP w0.254: U101.J11 v6(35.64,49.98)
  L7_SIG w0.091: P502.15 78.62,52.6 78.53,52.69 77.85,52.69 77.54,52.38 77.54,51.03 76.12,49.62 75.42,49.62 73.48,47.67 52.21,47.67 51.6,48.28 49.44,48.28 49.09,47.93 42.55,47.93 42.02,47.4 39.99,47.4 39.79,47.2 39.48,47.2 39.26,47.42 38.77,47.42 38.14,48.05 37.9,48.05 37.71,48.24 37.71,48.48 37.34,48.85 37.1,48.85 36.91,49.04 36.91,49.31 36.83,49.39 36.7,49.39 36.54,49.54 36.07,49.54 v6(35.64,49.98)
  L8_SIG w0.091: v2(136.56,35.18) 136.15,34.77 136.15,34.2 135.45,33.49 130.23,33.49 128.36,35.36 125.52,35.36 113.21,47.67 102.75,47.67 97.78,52.65 95.87,52.65 94.96,53.56 94.96,54.59 94.14,55.42 85.82,55.42 85.13,54.74 85.13,53.41 84.42,52.7 79.29,52.7 78.62,52.03 P502.15
  BOTTOM w0.203: v2(136.56,35.18) P801.G31
GPIO_14: length 121.8
  TOP w0.254: U101.K11 v6(36.44,49.98)
  L7_SIG w0.091: v6(36.44,49.98) 36.47,49.98 36.8,49.64 36.94,49.64 37.08,49.5 37.37,49.5 37.56,49.31 37.56,48.99 37.85,48.7 38.17,48.7 38.36,48.51 38.36,48.19 38.88,47.67 39.2,47.67 39.48,47.95 39.79,47.95 40.1,47.65 41.92,47.65 42.45,48.18 48.98,48.18 49.34,48.54 51.7,48.54 52.31,47.93 73.37,47.93 75.32,49.87 76.02,49.87 77.29,51.14 77.29,52.49 77.74,52.94 78.97,52.94 79.1,53.07 79.1,53.96 78.97,54.09 P502.16
  L8_SIG w0.091: P502.16 78.62,53.62 79.29,52.95 84.32,52.95 84.88,53.52 84.88,54.84 85.71,55.67 94.24,55.67 95.22,54.7 95.22,53.66 95.98,52.9 97.88,52.9 102.86,47.93 113.31,47.93 125.62,35.62 128.46,35.62 130.34,33.74 135.34,33.74 135.9,34.3 135.9,34.87 135.59,35.18 v2(135.29,35.18)
  BOTTOM w0.203: v2(135.29,35.18) P801.G30
GPIO_15: length 147
  TOP w0.254: U101.L11 v6(37.24,49.98)
  L5_SIG w0.091: P502.17 76.84,51.55 78.17,52.88 79.1,52.88 79.86,53.64 79.86,54.84 81.01,55.99 85.67,55.99 85.86,56.18 97.4,56.18 99.3,54.28 102.98,54.28 103.24,54.02 123.96,54.02 124.22,53.77 130.06,53.77 131.33,52.5 136.91,52.5 139.06,50.35 139.06,42.46 138.6,42 135.86,42 135.29,42.57 v2(135.29,42.8)
  L10_SIG w0.091: P502.17 75.07,51.55 74.88,51.35 74.88,50.47 75.08,50.26 76.65,50.26 77.13,50.74 77.74,50.74 78.17,50.31 79.06,50.31 79.52,50.77 80.08,50.77 80.46,50.39 83.2,50.39 83.33,50.26 83.33,49.75 83.2,49.62 79.89,49.62 79.85,49.58 79.43,49.58 79.39,49.62 73.55,49.62 70.21,52.96 46.27,52.96 44.56,54.66 37.86,54.66 36.79,53.59 36.79,50.07 36.88,49.98 v6(37.24,49.98)
  BOTTOM w0.203: P801.G24 v2(135.29,42.8)
GPIO_16: length 112.5
  TOP w0.254: U101.M11 v6(38.04,49.98)
  L5_SIG w0.091: P502.18 74.72,52.72 74.72,52.59 74.9,52.41 75.03,52.41 75.52,52.9 76.36,52.9 77.27,53.81 77.27,55.46 79.37,57.56 80.35,57.56 80.9,57.02 103.04,57.02 104.76,55.29 114.58,55.29 116.49,57.2 122.03,57.2 122.54,56.69 132.34,56.69 132.72,56.32 135.51,56.32 136.06,55.77 136.06,54.32 136.15,54.23 v2(136.56,54.23)
  L7_SIG w0.091: v6(38.04,49.98) 38.35,49.98 38.82,49.5 40.83,49.5 41.03,49.7 47.78,49.7 48.8,50.72 70.29,50.72 72.56,52.99 74.98,52.99 P502.18
  BOTTOM w0.394: P801.G16 v2(136.56,54.23)
GPIO_17: length 112.5
  TOP w0.254: U101.M10 v6(38.04,49.18)
  L5_SIG w0.091: P502.19 74.53,51.55 75.63,52.65 76.46,52.65 77.52,53.71 77.52,55.36 79.48,57.31 80.25,57.31 80.79,56.76 102.93,56.76 104.66,55.04 114.69,55.04 116.59,56.94 121.93,56.94 122.44,56.43 132.24,56.43 132.61,56.06 135.4,56.06 135.8,55.67 135.8,54.74 v2(135.29,54.23)
  L7_SIG w0.091: P502.19 74.89,51.55 74.99,51.64 74.99,52.57 74.83,52.73 72.66,52.73 70.4,50.47 48.9,50.47 47.89,49.45 41.14,49.45 40.93,49.25 40.02,49.25 39.94,49.16 39.94,48.98 39.75,48.79 39.47,48.79 39.22,49.04 39.16,49.04 38.91,48.79 38.77,48.79 38.38,49.18 v6(38.04,49.18)
  BOTTOM w0.394: P801.G15 v2(135.29,54.23)
GPIO_18: length 125.2
  TOP w0.254: U101.J3 v6(35.64,43.58)
  TOP w0.305: R518.1 R521.1 73.66,56.13 73.66,54.2 P502.20
  L5_SIG w0.114: P502.20 73.54,54.15 79.26,59.87 87.16,59.87 87.17,59.86 100.59,59.86 105.22,64.49 124.97,64.49 127.12,62.34 129.36,62.34 130.44,61.26 137.15,61.26 v2(140.37,58.04)
  L8_SIG w0.097: 39.41,46.38 39.76,46.38
  L8_SIG w0.114: v6(35.64,43.58) 35.47,43.58 35.01,44.04 35.01,45.68 35.19,45.85 35.19,46.02 36.28,47.11 36.58,47.11 36.85,46.84 36.85,46.62 37.08,46.38 39.41,46.38 ; 39.76,46.38 39.78,46.38 40.52,45.64 47.36,45.64 48.95,47.22 50.3,47.22 50.39,47.13 51.38,47.13 51.39,47.14 54.1,47.14 54.29,47.32 59.6,47.32 60.33,48.05 67.72,48.05 73.54,53.87 P502.20
  BOTTOM w0.203: v2(140.37,58.04) 139.92,58.49 139.88,58.49 139.74,58.63 P801.D12
INPUT_VOLTAGE: length 42.1
  TOP w0.203: CR701.C 121.36,18.14 DS701.A
  TOP w0.305: R602.2 v1(55.9,19.99)
  L7_SIG w0.114: v1(55.9,19.99) 56.41,19.48 60.21,19.48 62.37,17.32 80.18,17.32 v1(84.09,21.22)
  BOTTOM w0.254: U701.6 92.24,26.12 v1(92.49,25.87) ; v1(92.49,25.87) 92.8,25.87 v1(93.15,25.51) ; v1(92.49,25.87) 92.24,25.62 U701.7 ; U701.38 85.75,29.8 85.26,30.29 ; U701.36 84.03,28.62 83.53,29.12 ; v1(85.59,21.2) 86.25,21.86 U701.22
  BOTTOM w0.394: R709.1 v1(92.94,31.09)
  vias: v1(83.38,30.98) v1(83.71,29.43) v1(84.24,30.98) v1(84.57,29.43) v1(84.82,21.2) v1(98.77,26.02) v1(98.77,25.13) v1(98.77,24.27) v7(117.74,18.72) v7(117.74,17) v7(119.26,18.72) v7(119.26,17) v7(123.71,18.72) v7(123.71,17) v7(125.23,18.72) v7(125.23,17)
JTAG_TDI: length 1.6
  TOP w0.305: v2(140.37,35.18) 140.04,34.85 R815.2
  BOTTOM w0.394: v2(140.37,35.18) P801.D30
JTAG_TDO: length 1.6
  TOP w0.305: R815.1 140.07,34.21 v2(140.37,33.91)
  BOTTOM w0.394: v2(140.37,33.91) P801.D31
LDO_VCO_2P5: length 3.4
  BOTTOM w0.254: C413.1 86.31,65.96 86.26,66.01 C412.1 86.26,66.94 86.55,67.23 86.55,67.74 86.54,67.75 86.54,68.07 U401.15
LF_EXT_CAP: length 3.1
  BOTTOM w0.203: 90.4,66.59 C410.2
  BOTTOM w0.254: R415.2 89.95,66.58 89.96,66.59 90.4,66.59 ; C410.2 90.54,66.69 90.54,67.88 U401.7
LF_PLL2: length 2.2
  BOTTOM w0.254: C412.2 87.25,67.31 87.04,67.52 U401.14
ORX1+: length 7.6
  BOTTOM w0.203: 23.26,54.75 C231.2 23.26,54.75 ; 23.26,54.75 arc(23.39,54.7) 23.49,54.6 ; 23.26,54.75 arc(23.39,54.7) 23.49,54.6 ; C232.2 L232.1 24,53.89 arc(24.06,53.79) 24.13,53.7 arc(25.74,51.94) 27.71,50.6 arc(28.06,50.47) 28.43,50.42 arc(28.64,50.41) v5(28.84,50.38)
ORX1-: length 7.5
  BOTTOM w0.203: C232.1 L232.2 24.29,54.09 arc(24.35,54) 24.42,53.9 arc(25.98,52.21) 27.87,50.92 arc(28.14,50.81) 28.43,50.78 arc(28.52,50.78) 28.61,50.8 arc(28.71,50.85) 28.8,50.91 arc(28.86,51.04) v5(28.84,51.18) ; 23.72,55.07 R230.2 23.72,55.07 arc(23.72,54.93) 23.78,54.8 arc(23.72,54.93) 23.72,55.07
ORX2+: length 7
  BOTTOM w0.203: C239.2 23.72,38.48 arc(23.72,38.62) 23.78,38.75 ; C240.2 L240.1 24.29,39.46 arc(25.89,41.26) 27.87,42.64 arc(28.14,42.74) 28.43,42.78 arc(28.52,42.77) 28.61,42.75 arc(28.71,42.71) 28.8,42.64 arc(28.86,42.51) v5(28.84,42.38)
ORX2-: length 7.1
  BOTTOM w0.203: C240.1 L240.2 24,39.66 arc(25.65,41.53) 27.71,42.95 arc(28.06,43.09) 28.43,43.13 arc(28.64,43.14) v5(28.84,43.18) ; C238.2 23.26,38.81 arc(23.39,38.86) 23.49,38.95
OUT: length 4.9
  BOTTOM w0.203: R410.1 110.48,72.15 111.2,71.42 Y402.4 Y403.3 Y401.4
RESETB: length 117.3
  TOP w0.254: U101.J4 v6(35.64,44.38)
  TOP w0.394: R802.1 128.26,61.2 TP804.1
  L5_SIG w0.114: TP804.1 127.59,61.01 118.63,61.01 117.35,59.73 117.1,59.73 113.55,56.18 106.31,56.18 103.8,58.69 79.1,58.69 74.81,54.4 74.81,53.64 74.09,52.92 v5(40.9,52.92) 40.83,52.92 39.89,51.98 38.65,51.98 38.44,51.78 38.44,48.22 39.23,47.44 39.23,46.62 39.22,46.61 39.22,45.04 39,44.81 38.74,44.81 38.44,44.51 38.44,44.23 38.14,43.93 36.08,43.93 v6(35.64,44.38)
  BOTTOM w0.305: R502.2 40.16,51.31 40.9,52.05 v5(40.9,52.92)
RX1+: length 7.9
  TOP w0.203: C207.1 L207.1 ; L207.1 arc(23.52,51.32) 23.76,51.2 27.51,48.53 arc(27.95,48.3) 28.44,48.22 arc(28.58,48.19) 28.7,48.11 U101.A9 ; L207.1 arc(23.16,51.34) 23.07,51.36 arc(22.61,51.29) 22.2,51.08
RX1-: length 7.9
  TOP w0.203: U101.A10 28.74,48.68 arc(28.63,48.6) 28.5,48.58 28.44,48.58 arc(28.06,48.64) 27.73,48.82 27.72,48.82 23.96,51.49 23.75,51.61 arc(23.51,51.71) L207.2 ; 23.06,51.72 23.07,51.71 23.06,51.71 arc(23.16,51.73) L207.2 ; C207.2 L207.2 ; 23.07,51.71 arc(22.61,51.78) R206.2
RX1_ENABLE: length 64.2
  TOP w0.254: U101.M5 v6(38.04,44.38)
  TOP w0.305: P501.7 76.27,65.01 R508.1
  L5_SIG w0.114: P501.7 75.51,64.94 74.3,66.15 73.3,66.15 71.89,64.74 71.89,60.12 69.34,57.56 40.89,57.56 38.36,55.04 37.35,55.04 36.08,53.77 36.08,52.96 35.3,52.19 35.3,47.43 35.49,47.24 35.69,47.24 36.06,46.87 36.06,46.03 36.77,45.32 36.77,45.16 37.2,44.74 37.67,44.74 v6(38.04,44.38)
  BOTTOM w0.203: 76.21,66.42 P501.7
RX2+: length 7.9
  TOP w0.203: C216.1 23.25,41.81 ; 23.25,41.81 arc(23.16,41.82) 23.06,41.84 ; 23.25,41.81 arc(23.51,41.84) 23.75,41.94 23.96,42.06 27.72,44.73 27.73,44.74 arc(28.06,44.91) 28.44,44.97 28.5,44.97 arc(28.63,44.95) 28.74,44.87 U101.A5 ; 23.06,41.84 23.07,41.84 23.06,41.84 ; 23.07,41.84 arc(22.61,41.77) 22.2,41.56
RX2-: length 7.9
  TOP w0.203: 23.25,42.22 L216.2 23.25,42.33 ; 23.25,42.22 arc(23.52,42.24) 23.76,42.35 27.51,45.02 arc(27.95,45.25) 28.44,45.33 arc(28.58,45.36) 28.7,45.44 U101.A6 ; 23.25,42.22 arc(23.16,42.21) 23.07,42.19 arc(22.61,42.26) 22.2,42.47
RX2_ENABLE: length 53.4
  TOP w0.254: U101.M7 v6(38.04,46.78)
  TOP w0.305: P501.8 76.27,62.34 R509.1
  L5_SIG w0.114: v6(38.04,46.78) 38.37,47.11 38.37,47.72 38.05,48.04 37.9,48.04 37.63,48.31 37.63,48.54 37.63,48.54 37.63,51.88 38.49,52.74 40.09,52.74 41.68,54.33 68.71,54.33 76.21,61.83 P501.8
  BOTTOM w0.203: 76.21,60.93 P501.8
RX_EXTLO+: length 6.7
  TOP w0.203: U101.B8 v6(29.24,47.58)
  L10_SIG w0.091: v6(29.24,47.58) 29.24,46.9 arc(29.19,46.77) 29.06,46.72 28.68,46.72 arc(28.62,46.73) 28.57,46.76 arc(28.42,46.87) 28.23,46.9 24.96,46.9 arc(24.74,46.95) v5(24.56,47.07)
  BOTTOM w0.203: C332.2 v5(24.56,47.07)
RX_EXTLO-: length 6.6
  TOP w0.203: U101.B7 v6(29.24,45.98)
  L10_SIG w0.091: v6(29.24,45.98) 29.24,46.29 arc(29.19,46.41) 29.06,46.47 28.68,46.47 arc(28.52,46.5) 28.39,46.58 arc(28.32,46.63) 28.23,46.65 24.99,46.65 arc(24.68,46.52) 24.56,46.22 v5(24.56,46.15)
  BOTTOM w0.203: C333.2 v5(24.56,46.15)
SERDIN0+: length 3
  BOTTOM w0.203: C508.1 146.02,40.57 arc(145.87,40.47) 145.7,40.44 143.75,40.44 arc(143.61,40.5) 143.55,40.64 P801.A26
SERDIN0-: length 3
  BOTTOM w0.203: P801.A27 143.55,39.88 arc(143.61,40.02) 143.75,40.08 145.7,40.08 arc(145.87,40.05) 146.02,39.95 C507.1
SERDIN1+: length 1.4
  TOP w0.203: v2(141.64,70.74) C510.1
  BOTTOM w0.203: P801.C2 v2(141.64,70.74)
SERDIN1-: length 2.2
  TOP w0.203: C509.1 v2(141.64,69.47) C509.1
  BOTTOM w0.203: 141.19,69.92 141.19,69.94 141.03,70.1 P801.C3 141.19,69.92 ; 141.19,69.92 v2(141.64,69.47)
SERDIN2+: length 3
  BOTTOM w0.203: C512.1 146.02,35.49 arc(145.87,35.39) 145.7,35.36 143.75,35.36 arc(143.61,35.42) 143.55,35.56 P801.A30
SERDIN2-: length 3
  BOTTOM w0.203: P801.A31 143.55,34.8 arc(143.61,34.94) 143.75,35 145.7,35 arc(145.87,34.97) 146.02,34.87 C511.1
SERDIN3+: length 3
  BOTTOM w0.203: P801.A22 143.55,45.72 arc(143.61,45.58) 143.75,45.52 145.7,45.52 arc(145.87,45.55) 146.02,45.65 C514.1
SERDIN3-: length 3
  BOTTOM w0.203: C513.1 146.02,45.03 arc(145.87,45.13) 145.7,45.16 143.75,45.16 arc(143.61,45.1) 143.55,44.96 P801.A23
SERDOUT0+: length 3
  BOTTOM w0.203: P801.A2 143.55,71.12 arc(143.61,70.98) 143.75,70.92 145.7,70.92 arc(145.87,70.95) 146.02,71.05 C516.1
SERDOUT0-: length 3
  BOTTOM w0.203: C515.1 146.02,70.43 arc(145.87,70.53) 145.7,70.56 143.75,70.56 arc(143.61,70.5) 143.55,70.36 P801.A3
SERDOUT1+: length 3
  BOTTOM w0.203: P801.A6 143.55,66.04 arc(143.61,65.9) 143.75,65.84 145.7,65.84 arc(145.87,65.87) 146.02,65.97 C518.1
SERDOUT1-: length 3
  BOTTOM w0.203: P801.A7 143.55,65.28 arc(143.61,65.42) 143.75,65.48 145.7,65.48 arc(145.87,65.45) 146.02,65.35 C517.1
SERDOUT2+: length 1.4
  TOP w0.203: v2(141.67,65.65) 141.67,65.63 C520.1
  BOTTOM w0.203: P801.C6 141.66,65.65 v2(141.67,65.65)
SERDOUT2-: length 1.4
  TOP w0.203: v2(141.64,64.39) C519.1
  BOTTOM w0.203: v2(141.64,64.39) P801.C7
SERDOUT3+: length 3
  BOTTOM w0.203: C522.1 146.02,60.89 arc(145.87,60.79) 145.7,60.76 143.75,60.76 arc(143.61,60.82) 143.55,60.96 P801.A10
SERDOUT3-: length 3
  BOTTOM w0.203: P801.A11 143.55,60.2 arc(143.61,60.34) 143.75,60.4 145.7,60.4 arc(145.87,60.37) 146.02,60.27 C521.1
SNRXA+: length 16.3
  TOP w0.254: U101.E4 v6(31.64,43.58)
  L10_SIG w0.091: v6(31.64,43.58) 31.74,43.47 31.82,43.4 arc(31.96,43.18) 32.01,42.92 32.01,41.99 arc(31.9,41.72) 31.62,41.6 arc(31.54,41.6) 31.47,41.58 arc(31.44,41.57) 31.42,41.56 arc(31.32,41.51) 31.24,41.44 arc(31.02,41.3) 30.76,41.24 30.6,41.24 arc(30.31,41.12) 30.18,40.83 30.18,36.18 arc(30.08,35.64) 29.77,35.17 29.71,35.12 arc(29.36,34.67) 29.11,34.17 arc(28.65,32.82) 28.25,31.47 arc(28.22,31.25) v5(28.25,31.04)
  BOTTOM w0.203: R222.2 27.72,29.55 arc(27.68,29.68) 27.71,29.82 ; C224.1 L224.1 28.09,30.79 arc(28.16,30.92) v5(28.25,31.04)
